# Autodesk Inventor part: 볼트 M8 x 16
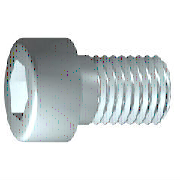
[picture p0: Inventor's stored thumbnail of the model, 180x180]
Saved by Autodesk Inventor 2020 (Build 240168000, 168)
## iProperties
IsCustomPart: 1
Created: 2012-02
Part Number: 볼트 M8 x 16
Material: 강철, 연강
Description: 원통형 머리 캡 나사
Document SubType Name: Modeling
Standard: JIS B 1176
Designer: mdu-01
Standards Organization: JIS
Language: ko-KR
Size Designation: M8 x 16
Categories: <MemberInstance><Categories><Category DisplayName="조임쇠" InternalName="e4da775c-781d-43d5-af7c-5136215cf5a6" Mnemonic="FSTN"><Category DisplayName="볼트" InternalN
Density: 1 g/cm^3
Appearance: 강철
Author: mdu-01
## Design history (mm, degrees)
sketch "스케치1"
  geometry: L1 (-2, 0)-(16, 0); L2 (16, 0)-(16, 4); L3 (16, 4)-(3.125, 4); L4 (3.125, 4)-(2.358, 4); L5 (2.358, 4)-(0, 4); L6 (0, 4)-(0, 6.5); L7 (0, 6.5)-(-8, 6.5); L8 (-8, 6.5)-(-8, 3.464); L9 (-8, 3.464)-(-4, 3.464); L10 (-4, 3.464)-(-2, 0); L11 (-12.8, 0)-(20.8, 0) reference; L12 (0, -1.3)-(0, 7.8) reference; L13 (3.125, 4)-(0, 4)
  constraints: 22 end point, 6 parallel, 2 collinear, 2 perpendicular, 1 horizontal, 1 point on line
  dimensions: "d1" = 12.875 distance from line of L3.end L2 (= GEL); "d2" = 0.76691 distance of L4.end L3.end (computed from GAL); "d3" = 8 distance between parallel lines of L8 L6 (= KOH); "d4" = 4 distance of L8.end L9.end (= INTI); "d5" = 60 deg angle of L10 L1; "d6" = 8 diameter of L3 L1 (= GD); "d7" = 8 diameter of L5 L1 (= BDM); "d8" = 6.9282 diameter of L9 L1 (= 1.1547 x SW); "d9" = 13 diameter of L7 L1 (= KOD); "d26" = 16 distance between parallel lines of L12 L2 (= NLG)
revolve "본체" sketch "스케치1" stored, may be unused: angle "d10" = 90 deg
sketch "스케치2"
  geometry: L1 (0, -9.1)-(0, 9.1) reference; L2 (-9.1, 0)-(9.1, 0) reference; L3 (3.464, 0)-(1.732, -3); L4 (1.732, -3)-(-1.732, -3); L5 (-1.732, -3)-(-3.464, 0); L6 (-3.464, 0)-(-1.732, 3); L7 (-1.732, 3)-(1.732, 3); L8 (1.732, 3)-(3.464, 0); 2 further points
  constraints: 12 end point, 1 coincident, 1 horizontal alignment, 1 point on line, 12 other
extrude "슬롯" join sketch "스케치2" stored distance "d11" = 10; taper "d12" = 0 deg
workplane "Work Plane1"
fillet "Fillet2" dims "d30" = 0.1 (= R)
body "Solid1"
fillet "모깎기1" dims "d17" = 0.8 (= RR)
feature "스레드" dims "d13" = 12.875 (= GEL), "d14" = 0
chamfer "모따기1" distance "d15" = 0.76681 (= -0.5 x SPD + 0.5 x GD); stored, may be unused: second distance "d16" = 0.76681 (= GUL), angle "d27" = 45 deg
other parameters: "GD" = 8 (= NND) [user parameter; used in 2 equation terms], "NLG" = 16 [user parameter; used in 1 equation term], "GEL" = 12.875 [user parameter; used in 2 equation terms], "KOD" = 13 [user parameter; used in 1 equation term], "KOH" = 8 [user parameter; used in 1 equation term], "INTI" = 4 [user parameter; used in 1 equation term], "GAL" = 0.76681 (= 0.61345 x PTC) [user parameter; used in 1 equation term], "GUL" = 0.76681 (= 0.61345 x PTC) [user parameter; used in 1 equation term], "BDM" = 8 (= NND) [user parameter; used in 1 equation term], "SW" = 6 [user parameter; used in 2 equation terms], "RR" = 0.8 [user parameter; used in 1 equation term], "SPD" = 6.46637 (= NND - 1.2269 x PTC) [user parameter; used in 1 equation term], "d19" = 0, "d28" = 0, "d29" = 0, "R" = 0.1 [user parameter; used in 1 equation term], "PHH" = 0.4 [user parameter], "GD1" = 6.46637 (= THREADDIA - 1.2269 x PTC) [user parameter], "THREADDIA" = 8 [user parameter; used in 1 equation term], "FAWI" = 45 deg [user parameter], "TPU" = 8 (computed from PTC) [user parameter], "PTC" = 1.25 [user parameter; used in 5 equation terms], "NND" = 8 [user parameter; used in 3 equation terms], "TOA" = 30 deg [user parameter], "E0" = 6.93 (= 1.155 x SW) [user parameter]
